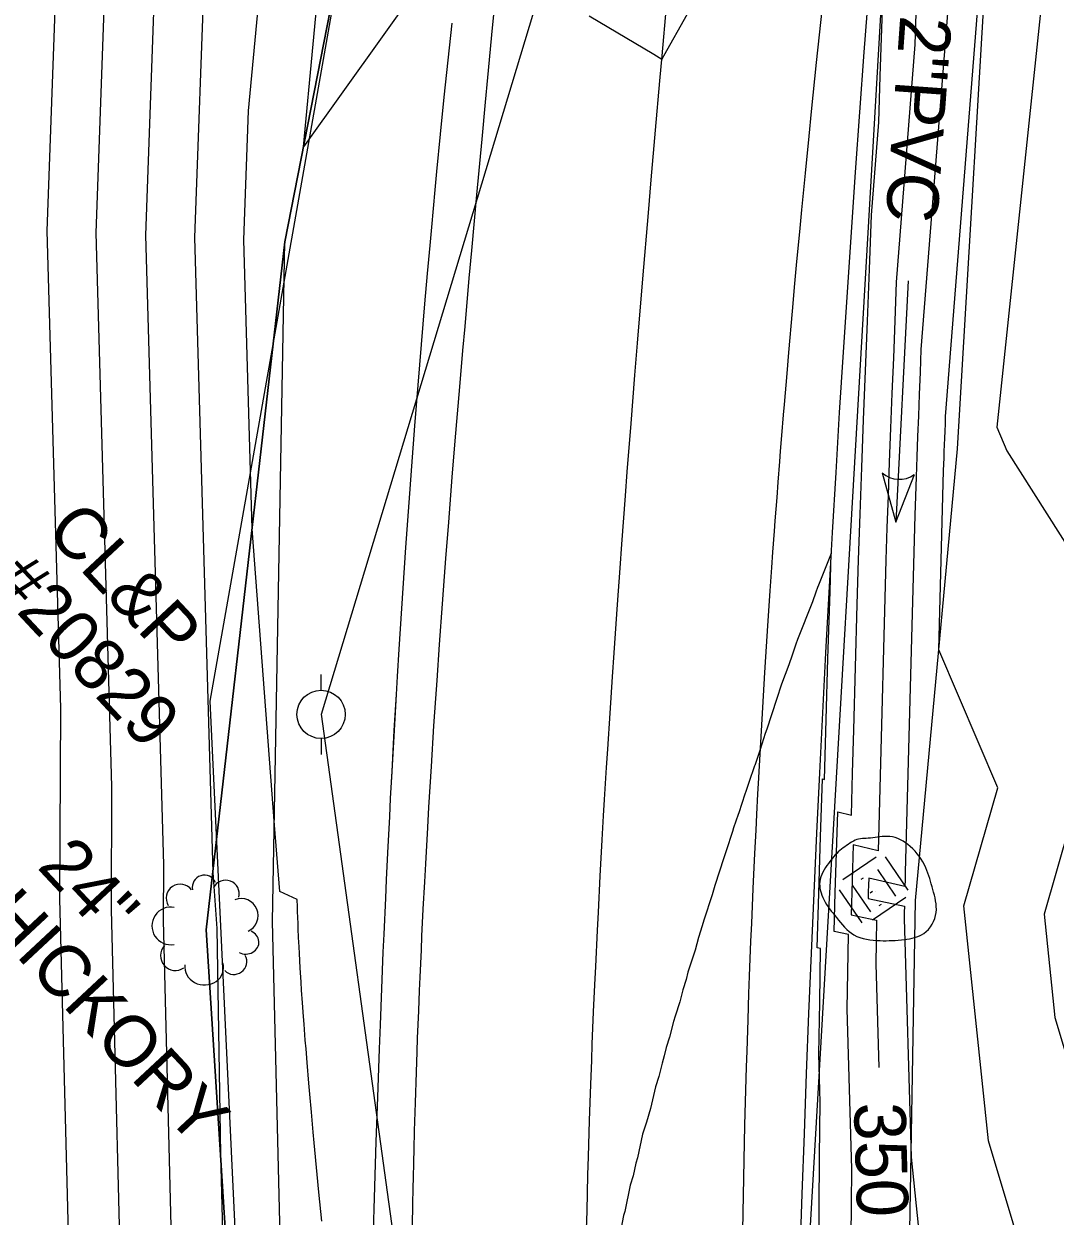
# Model space of a CAD drawing. Extents: x 487096 to 489566, y 221939 to 224454.
# Drawn here: x 488373.2 to 488437.3, y 222981.8 to 223055.9 of the extents above; entities that cross this region are included whole.
import ezdxf

# ---------------------------------------------------------------- set-up
doc = ezdxf.new("R2010")
doc.units = 0
for name, color, linetype in [('SV_BKLN_EARTH_TOP', 7, 'Continuous'), ('SV_FENC_FENCES', 7, 'Continuous'), ('SV_MISC_MISC_TOPO', 7, 'Continuous'), ('SV_PIPE_FLOW', 7, 'Continuous'), ('SV_PIPE_PLAS_12', 7, 'Continuous'), ('SV_PIPE_PLAS_TX', 7, 'Continuous'), ('SV_ROAD_BITRD', 7, 'Continuous'), ('SV_ROCK_MISC_ROCK', 7, 'Continuous'), ('SV_ROWL_HWYLOC', 7, 'Continuous'), ('SV_SURF_INDEX_CONTOUR', 7, 'Continuous'), ('SV_SURF_INTER_CONTOUR', 7, 'Continuous'), ('SV_TRAF_PVMTL', 7, 'Continuous'), ('SV_TREE_TREEVEG', 7, 'Continuous'), ('SV_TREE_TREEVEG_TX', 7, 'Continuous'), ('SV_UTOH_OVERHEAD_LINES', 7, 'Continuous'), ('SV_UTOH_UPO', 7, 'Continuous'), ('SV_UTOH_UTOH_TX', 7, 'Continuous')]:
    doc.layers.add(name, color=color, linetype=linetype)

msp = doc.modelspace()

# ---------------------------------------------------------------- linework, layer by layer
at = {"layer": 'SV_BKLN_EARTH_TOP'}
for points in [[(488425.924, 222945.038), (488428.157, 222977.235), (488428.574, 223001.384), (488431.193, 223029.446), (488433.274, 223064.759), (488435.624, 223093.089), (488438.489, 223133.722), (488441.679, 223167.826), (488447.058, 223190.641), (488452.004, 223226.545)], [(488391.814, 222875.894), (488390.567, 222921.008), (488388.639, 223000.073), (488389.407, 223042.325), (488396.478, 223078.484), (488405.528, 223123.261), (488407.475, 223152.677)]]:
    msp.add_lwpolyline(points, dxfattribs=at)
at = {"layer": 'SV_FENC_FENCES'}
msp.add_lwpolyline([(488400.559, 222861.835), (488391.815, 222875.913), (488387.651, 222918.235), (488386.769, 222964.099), (488384.515, 222999.563), (488389.407, 223042.325), (488396.478, 223078.484), (488402.804, 223123.48), (488407.475, 223152.677), (488415.007, 223209.78), (488415.388, 223241.145)], dxfattribs=at)
at = {"layer": 'SV_MISC_MISC_TOPO'}
msp.add_line((488426.063, 223001.932), (488426.063, 223001.932), dxfattribs=at)
at = {"layer": 'SV_PIPE_FLOW'}
for p, q in [((488428.127, 223039.883), (488427.348, 223024.902)), ((488426.504, 223027.951), (488427.348, 223024.902)), ((488427.348, 223024.902), (488428.505, 223027.848))]:
    msp.add_line(p, q, dxfattribs=at)
msp.add_arc((488427.572, 223029.196), 1.639, 229.42502, 304.62665, dxfattribs=at)
at = {"layer": 'SV_PIPE_PLAS_12'}
msp.add_line((488420.272, 222950.354), (488430.688, 223129.857), dxfattribs=at)
at = {"layer": 'SV_ROAD_BITRD'}
for points in [[(488421.42, 222979.418), (488421.543, 222983.156), (488421.674, 222986.894), (488421.812, 222990.631), (488421.959, 222994.368), (488422.114, 222998.105), (488422.276, 223001.841), (488422.447, 223005.577), (488422.625, 223009.312), (488422.812, 223013.048), (488423.007, 223016.783), (488423.209, 223020.517), (488423.42, 223024.251), (488423.638, 223027.984), (488423.865, 223031.717), (488424.099, 223035.45), (488424.342, 223039.182), (488424.592, 223042.913), (488424.851, 223046.644), (488425.117, 223050.375), (488425.392, 223054.104), (488425.674, 223057.833)], [(488399.764, 223055.907), (488399.444, 223052.836), (488399.287, 223051.301), (488399.056, 223048.997), (488398.831, 223046.693), (488398.72, 223045.54), (488398.504, 223043.235), (488398.398, 223042.083), (488398.242, 223040.353), (488398.075, 223038.461), (488397.967, 223037.2), (488397.756, 223034.677), (488397.653, 223033.415), (488397.453, 223030.891), (488397.26, 223028.366), (488397.136, 223026.682), (488397.055, 223025.56), (488396.897, 223023.314), (488396.81, 223022.051), (488396.643, 223019.524), (488396.483, 223016.997), (488396.379, 223015.312), (488396.312, 223014.188), (488396.182, 223011.941), (488396.042, 223009.412), (488395.952, 223007.725), (488395.894, 223006.601), (488395.781, 223004.352), (488395.7, 223002.665), (488395.647, 223001.54), (488395.546, 222999.291), (488395.497, 222998.166), (488395.402, 222995.916), (488395.313, 222993.665), (488395.256, 222992.165), (488395.148, 222989.163), (488395.055, 222986.385), (488395.012, 222984.995), (488394.95, 222982.911), (488394.894, 222980.827)], [(488399.764, 223055.907), (488399.444, 223052.836), (488399.287, 223051.301), (488399.056, 223048.997), (488398.831, 223046.693), (488398.721, 223045.54), (488398.504, 223043.235), (488398.398, 223042.083), (488398.242, 223040.353), (488398.075, 223038.461), (488397.967, 223037.2), (488397.755, 223034.677), (488397.653, 223033.415), (488397.453, 223030.891), (488397.26, 223028.366), (488397.135, 223026.682), (488397.054, 223025.56), (488396.896, 223023.314), (488396.81, 223022.051), (488396.642, 223019.524), (488396.482, 223016.997), (488396.379, 223015.312), (488396.312, 223014.188), (488396.181, 223011.94), (488396.041, 223009.411), (488395.951, 223007.725), (488395.893, 223006.601), (488395.78, 223004.352), (488395.699, 223002.665), (488395.647, 223001.54), (488395.545, 222999.291), (488395.496, 222998.166), (488395.402, 222995.916), (488395.313, 222993.665), (488395.256, 222992.165), (488395.148, 222989.163), (488395.056, 222986.385), (488395.012, 222984.995), (488394.951, 222982.911), (488394.895, 222980.827)], [(488399.764, 223055.907), (488399.444, 223052.836), (488399.287, 223051.301), (488399.056, 223048.997), (488398.831, 223046.693), (488398.721, 223045.54), (488398.504, 223043.235), (488398.398, 223042.083), (488398.242, 223040.353), (488398.075, 223038.461), (488397.967, 223037.2), (488397.755, 223034.677), (488397.653, 223033.415), (488397.453, 223030.891), (488397.26, 223028.366), (488397.135, 223026.682), (488397.054, 223025.56), (488396.896, 223023.314), (488396.81, 223022.051), (488396.642, 223019.524), (488396.482, 223016.997), (488396.379, 223015.312), (488396.312, 223014.188), (488396.181, 223011.94), (488396.041, 223009.411), (488395.951, 223007.725), (488395.893, 223006.601), (488395.78, 223004.352), (488395.699, 223002.665), (488395.647, 223001.54), (488395.545, 222999.291), (488395.496, 222998.166), (488395.402, 222995.916), (488395.313, 222993.665), (488395.256, 222992.165), (488395.148, 222989.163), (488395.056, 222986.385), (488395.012, 222984.995), (488394.951, 222982.911), (488394.895, 222980.827)]]:
    msp.add_lwpolyline(points, dxfattribs=at)
at = {"layer": 'SV_ROCK_MISC_ROCK'}
for p, q in [((488426.211, 223003.315), (488427.338, 223001.663)), ((488424.648, 223002.338), (488425.779, 223000.688))]:
    msp.add_line(p, q, dxfattribs=at)
for points in [[(488426.128, 223004.078), (488424.063, 223002.666)], [(488426.696, 223004.092), (488428.109, 223002.028)], [(488425.319, 223002.776), (488425.183, 223002.684)], [(488423.831, 223002.057), (488425.242, 222999.995)], [(488425.896, 223001.935), (488425.76, 223001.843)], [(488427.975, 223001.579), (488425.914, 223000.168)], [(488426.438, 223001.141), (488426.307, 223001.049)]]:
    msp.add_lwpolyline(points, dxfattribs=at)
msp.add_spline([(488424.715, 223005.074), (488423.879, 223004.493), (488423.164, 223003.694), (488422.629, 223002.566), (488422.874, 223001.445), (488423.673, 223000.321), (488424.75, 222999.249), (488426.377, 222998.891), (488427.886, 222998.964), (488429.09, 222999.333), (488429.856, 223000.646), (488429.654, 223002.071), (488429.213, 223003.421), (488428.25, 223004.746), (488426.972, 223005.363), (488426.787, 223005.369), (488425.641, 223005.251), (488424.718, 223005.076), (488424.705, 223005.067)], degree=3, dxfattribs=at)
at = {"layer": 'SV_ROWL_HWYLOC'}
msp.add_lwpolyline([(488415.388, 223241.145), (488415.007, 223209.78), (488407.475, 223152.677), (488402.804, 223123.48), (488396.478, 223078.484), (488389.407, 223042.325), (488386.961, 223020.944), (488384.515, 222999.563), (488386.769, 222964.099), (488387.651, 222918.235), (488391.815, 222875.913), (488394, 222859.238), (488415.207, 222774.386)], dxfattribs=at)
at = {"layer": 'SV_SURF_INDEX_CONTOUR'}
for points in [[(488379.351, 222972.188), (488378.624, 223000.814), (488378.664, 223008.462), (488377.682, 223042.865), (488378.243, 223058.541)], [(488428.598, 223056.513), (488428.537, 223054.572), (488427.374, 223039.801), (488427.286, 223037.416), (488427.206, 223035.111), (488427.112, 223032.9), (488427.025, 223030.738), (488426.945, 223028.624), (488426.87, 223026.557), (488426.802, 223024.535), (488426.739, 223022.557), (488426.339, 223007.564), (488426.294, 223006), (488426.253, 223004.478), (488424.711, 223004.835), (488424.66, 223003.346), (488424.613, 223001.897), (488424.571, 223000.486), (488426.153, 223000.155), (488426.128, 222998.79), (488426.106, 222997.459), (488426.291, 222991)]]:
    msp.add_lwpolyline(points, dxfattribs=at)
at = {"layer": 'SV_SURF_INTER_CONTOUR'}
for points in [[(488393.727, 223230.342), (488395.957, 223208.567), (488396.766, 223191.599), (488396.761, 223190.004), (488396.754, 223188.935), (488396.731, 223186.785), (488396.715, 223185.704), (488396.675, 223183.531), (488399.104, 223174.552), (488399.019, 223172.338), (488398.956, 223170.854), (488398.077, 223154.84), (488399.462, 223145.879), (488397.97, 223122.923), (488395.516, 223114.366), (488386.678, 223084.046), (488384.425, 223060.17), (488383.795, 223042.583), (488384.921, 223003.118), (488385.182, 222999.645), (488385.401, 222985.627), (488385.932, 222964.714)], [(488388.002, 223227.487), (488389.978, 223208.186), (488390.695, 223193.147), (488390.691, 223191.733), (488390.684, 223190.786), (488390.664, 223188.88), (488390.65, 223187.922), (488390.615, 223185.996), (488393.85, 223174.037), (488393.772, 223172.014), (488393.714, 223170.658), (488392.911, 223156.028), (488395.058, 223142.143), (488393.778, 223122.441), (488389.196, 223106.462), (488383.231, 223086.001), (488381.711, 223069.889), (488380.739, 223042.724), (488381.855, 223003.609), (488381.837, 223000.132), (488382.676, 222967.106)], [(488376.551, 223221.776), (488378.02, 223207.425), (488378.553, 223196.243), (488378.55, 223195.191), (488378.545, 223194.487), (488378.53, 223193.07), (488378.52, 223192.358), (488378.493, 223190.925), (488383.341, 223173.007), (488383.277, 223171.367), (488383.231, 223170.267), (488382.579, 223158.405), (488386.25, 223134.67), (488385.392, 223121.475), (488376.555, 223090.655), (488376.339, 223089.913), (488376.284, 223089.329), (488374.625, 223043.005), (488375.473, 223013.316), (488375.412, 223001.496), (488376.164, 222971.889)], [(488444.738, 223139.906), (488443.486, 223134.795), (488442.207, 223128.85), (488437.705, 223095.548), (488437.641, 223093.606), (488437.615, 223090.913), (488437.236, 223067.257), (488438.303, 223064.405), (488437.196, 223062.974), (488436.493, 223057.978), (488433.618, 223030.808), (488434.258, 223029.334), (488441.028, 223018.654), (488441.049, 223018.096), (488440.962, 223017.32), (488440.482, 223014.189), (488436.564, 223000.533), (488437.239, 222994.108), (488442.853, 222975.364)], [(488391.692, 222981.463), (488391.519, 222983.268), (488391.415, 222984.36), (488391.232, 222986.321), (488391.17, 222986.988), (488391.058, 222988.227), (488390.957, 222989.351), (488390.897, 222990.044), (488390.787, 222991.314), (488390.716, 222992.176), (488390.672, 222992.713), (488390.593, 222993.708), (488390.557, 222994.169), (488390.494, 222995.028), (488390.439, 222995.814), (488390.406, 222996.302), (488390.35, 222997.204), (488390.301, 222998.086), (488390.281, 222998.496), (488390.254, 222999.08), (488390.231, 222999.63), (488390.221, 222999.893), (488390.204, 223000.4), (488390.196, 223000.644), (488390.186, 223001), (488390.175, 223001.455), (488389.082, 223001.948), (488388.748, 223006.075), (488387.365, 223024.474), (488386.852, 223042.443), (488387.138, 223050.45), (488390.124, 223082.09)], [(488400.328, 223061.911), (488390.558, 223048.214), (488393.57, 223080.134)], [(488436.184, 222976.213), (488433.118, 222986.451), (488431.583, 223001.063), (488433.686, 223008.391), (488430.028, 223016.964), (488430.325, 223028.103), (488430.337, 223028.489), (488430.351, 223028.883), (488430.365, 223029.286), (488430.381, 223029.697), (488430.398, 223030.119), (488430.416, 223030.55), (488430.432, 223030.999), (488430.449, 223031.463), (488433.028, 223064.23)], [(488430.783, 223059.401), (488428.912, 223035.632), (488428.859, 223034.208), (488428.811, 223032.831), (488428.755, 223031.509), (488428.703, 223030.218), (488428.655, 223028.955), (488428.61, 223027.72), (488428.57, 223026.512), (488428.532, 223025.33), (488427.94, 223003.137), (488427.927, 223002.693), (488427.916, 223002.261), (488425.667, 223002.783), (488425.652, 223002.346), (488425.638, 223001.922), (488425.626, 223001.509), (488427.887, 223001.035), (488427.88, 223000.648), (488427.874, 223000.271), (488428.299, 222985.434), (488428.996, 222978.793)], [(488424.583, 222980.435), (488424.601, 222982.533), (488424.623, 222984.696), (488424.338, 222994.648), (488424.376, 222996.931), (488424.419, 222999.275), (488423.516, 222999.464), (488423.588, 223001.873), (488423.668, 223004.346), (488423.755, 223006.888), (488424.59, 223006.695), (488424.66, 223009.306), (488424.739, 223011.992), (488424.946, 223019.783), (488425.034, 223022.558), (488425.13, 223025.394), (488425.234, 223028.293), (488425.347, 223031.258), (488425.47, 223034.29), (488425.601, 223037.392), (488425.714, 223040.625), (488425.837, 223043.969), (488426.292, 223049.743), (488426.381, 223052.603), (488426.481, 223055.577), (488426.592, 223058.67)], [(488414.394, 223056.462), (488412.931, 223053.861), (488412.817, 223053.655), (488412.325, 223053.949), (488408.3, 223056.348)], [(488422.574, 222979.044), (488422.594, 222982.216), (488422.621, 222985.483), (488422.656, 222988.85), (488422.57, 222991.837), (488422.624, 222995.073), (488422.685, 222998.395), (488422.461, 222998.442), (488422.563, 223001.848), (488422.676, 223005.346), (488422.798, 223008.941), (488422.926, 223008.911), (488423.027, 223012.613), (488423.138, 223016.42), (488423.153, 223017.01), (488423.266, 223020.581), (488423.347, 223022.954), (488422.556, 223020.99), (488422.495, 223020.83), (488422.387, 223020.541), (488422.171, 223019.953), (488421.252, 223017.596), (488421.15, 223017.305), (488420.916, 223016.635), (488420.71, 223016.037), (488420.254, 223014.832), (488419.938, 223013.871), (488419.34, 223012.027), (488419.241, 223011.755), (488418.936, 223010.761), (488418.596, 223009.782), (488418.584, 223009.748), (488418.232, 223008.725), (488418.035, 223008.149), (488417.983, 223007.988), (488417.593, 223006.839), (488417.555, 223006.72), (488417.277, 223005.893), (488417.207, 223005.668), (488416.807, 223004.47), (488416.675, 223004.028), (488416.113, 223002.326), (488415.944, 223001.74), (488415.433, 223000.173), (488415.334, 222999.818), (488415.099, 222999.092), (488414.882, 222998.293), (488414.442, 222996.924), (488414.322, 222996.467), (488414.12, 222995.836), (488413.93, 222995.092), (488413.646, 222994.2), (488413.541, 222993.87), (488413.298, 222992.888), (488413.098, 222992.254), (488412.971, 222991.726), (488412.83, 222991.279), (488412.632, 222990.441), (488412.435, 222989.813), (488412.123, 222988.451), (488411.861, 222987.606), (488411.627, 222986.864), (488411.309, 222985.392), (488411.205, 222985.062), (488411.041, 222984.283), (488410.856, 222983.691), (488410.524, 222982.058), (488410.444, 222981.802), (488410.274, 222980.943)]]:
    msp.add_lwpolyline(points, dxfattribs=at)
at = {"layer": 'SV_TRAF_PVMTL'}
for points in [[(488402.628, 223059.065), (488402.289, 223055.609), (488401.993, 223052.537), (488401.846, 223051.001), (488401.629, 223048.696), (488401.308, 223045.239), (488400.993, 223041.781), (488400.837, 223040.051), (488400.572, 223037.057), (488400.442, 223035.56), (488400.249, 223033.314), (488399.966, 223029.944), (488399.782, 223027.697), (488399.691, 223026.574), (488399.558, 223024.888), (488399.383, 223022.641), (488399.298, 223021.517), (488399.172, 223019.83), (488398.989, 223017.301), (488398.832, 223015.052), (488398.755, 223013.928), (488398.643, 223012.241), (488398.482, 223009.71), (488398.328, 223007.18), (488398.254, 223005.914), (488398.129, 223003.664), (488398.068, 223002.539), (488397.981, 223000.851), (488397.899, 222999.162), (488397.859, 222998.318), (488397.782, 222996.63), (488397.746, 222995.786), (488397.693, 222994.519), (488397.627, 222992.831), (488397.596, 222991.986), (488397.551, 222990.72), (488397.489, 222988.819), (488397.438, 222987.075), (488397.406, 222985.912), (488397.387, 222985.136), (488397.362, 222984.102), (488397.351, 222983.585), (488397.326, 222982.422), (488397.284, 222980.095)], [(488408.145, 222980.959), (488408.171, 222982.084), (488408.227, 222984.334), (488408.259, 222985.46), (488408.329, 222987.71), (488408.406, 222989.961), (488408.462, 222991.462), (488408.501, 222992.462), (488408.584, 222994.463), (488408.659, 222996.151), (488408.71, 222997.276), (488408.819, 222999.527), (488408.876, 223000.653), (488408.994, 223002.904), (488409.119, 223005.154), (488409.205, 223006.655), (488409.264, 223007.655), (488409.385, 223009.656), (488409.455, 223010.781), (488409.6, 223013.031), (488409.749, 223015.281), (488409.851, 223016.781), (488410.061, 223019.781), (488410.223, 223022.03), (488410.334, 223023.53), (488410.56, 223026.529), (488410.675, 223028.028), (488410.91, 223031.025), (488411.149, 223034.022), (488411.312, 223036.02), (488411.641, 223040.014), (488411.986, 223044.119), (488412.161, 223046.172), (488412.427, 223049.249), (488412.698, 223052.326), (488412.835, 223053.865), (488413.114, 223056.94)], [(488417.848, 222980.886), (488417.866, 222981.976), (488417.907, 222984.157), (488417.93, 222985.247), (488417.981, 222987.427), (488418.038, 222989.606), (488418.08, 222991.059), (488418.11, 222992.028), (488418.152, 222993.319), (488418.173, 222993.965), (488418.231, 222995.599), (488418.271, 222996.688), (488418.357, 222998.866), (488418.402, 222999.955), (488418.497, 223002.133), (488418.598, 223004.31), (488418.669, 223005.761), (488418.718, 223006.729), (488418.785, 223008.019), (488418.82, 223008.663), (488418.879, 223009.751), (488419.002, 223011.927), (488419.131, 223014.103), (488419.221, 223015.553), (488419.282, 223016.519), (488419.365, 223017.808), (488419.407, 223018.452), (488419.554, 223020.626), (488419.655, 223022.075), (488419.724, 223023.041), (488419.818, 223024.329), (488419.865, 223024.973), (488419.974, 223026.421), (488420.048, 223027.386), (488420.148, 223028.674), (488420.199, 223029.317), (488420.277, 223030.282), (488420.381, 223031.569), (488420.434, 223032.212), (488420.596, 223034.142), (488420.707, 223035.428), (488420.933, 223038), (488421.089, 223039.719), (488421.194, 223040.864), (488421.409, 223043.155), (488421.519, 223044.301), (488421.741, 223046.591), (488421.969, 223048.881), (488422.122, 223050.407), (488422.434, 223053.46), (488422.793, 223056.893)]]:
    msp.add_lwpolyline(points, dxfattribs=at)
at = {"layer": 'SV_TREE_TREEVEG'}
msp.add_line((488384.515, 222999.563), (488384.515, 222999.563), dxfattribs=at)
msp.add_lwpolyline([(488469.572, 222626.729), (488414.357, 222775.799), (488391.306, 222875.646), (488384.757, 223013.776), (488396.275, 223079.007), (488413.65, 223210.141), (488414.482, 223247.549), (488427.956, 223341.619), (488424.883, 223443.612), (488411.442, 223499.763), (488395.395, 223528.757), (488373.339, 223524.504)], dxfattribs=at)
for centre, radius, start, end in [((488384.404, 223002.214), 0.75, 23.2911, 192.35792), ((488385.719, 223001.8), 0.85, 345.53076, 152.70931), ((488382.904, 223001.527), 0.874, 35.99331, 211.459), ((488386.68, 223000.444), 1.059, 294.18586, 111.10825), ((488382.315, 222999.809), 1.171, 79.3292, 279.98885), ((488382.598, 222997.959), 0.922, 137.01566, 304.55007)]:
    msp.add_arc(centre, radius, start, end, dxfattribs=at)
for centre, major_axis, ratio, start_param, end_param in [((488386.97, 222998.796), (0.822, -0.013), 0.901056, 4.216583, 7.444153), ((488384.386, 222997.227), (-1.196, 0.159), 0.902156, 0, 3.5401), ((488386.234, 222997.594), (0.08, -0.798), 0.999752, 5.391582, 8.241319)]:
    msp.add_ellipse(centre, major_axis=major_axis, ratio=ratio, start_param=start_param, end_param=end_param, dxfattribs=at)
at = {"layer": 'SV_UTOH_OVERHEAD_LINES'}
msp.add_lwpolyline([(488477.012, 222631.438), (488424.125, 222778.25), (488391.68, 223012.955), (488449.873, 223205.72), (488469.995, 223438.334), (488349.561, 223622.886), (488159.178, 223693.118), (487993.175, 223755.783), (487804.196, 223830.216), (487742.262, 223860.212)], dxfattribs=at)
at = {"layer": 'SV_UTOH_UPO'}
for p, q in [((488391.658, 223014.429), (488391.658, 223015.431)), ((488391.671, 223010.457), (488391.671, 223011.456))]:
    msp.add_line(p, q, dxfattribs=at)
msp.add_circle((488391.651, 223012.95), 1.5, dxfattribs=at)

# ---------------------------------------------------------------- texts
at = {"layer": 'SV_PIPE_PLAS_TX'}
msp.add_text("12''PVC", height=3.2, rotation=265.91172, dxfattribs=at).set_placement((488427.804, 223058.799))
at = {"layer": 'SV_SURF_INDEX_CONTOUR'}
msp.add_text('350', height=3.2, rotation=271.64009, dxfattribs=at).set_placement((488424.753, 222988.807))
at = {"layer": 'SV_TREE_TREEVEG_TX'}
for s, p in [('24"', (488373.952, 223003.444)), ('HICKORY', (488370.516, 223000.236))]:
    msp.add_text(s, height=3.2, rotation=313.03859, dxfattribs=at).set_placement(p)
at = {"layer": 'SV_UTOH_UTOH_TX'}
for s, p in [('CL&P', (488374.476, 223024.274)), ('#20829', (488371.041, 223021.066))]:
    msp.add_text(s, height=3.2, rotation=313.03859, dxfattribs=at).set_placement(p)

doc.saveas('drawing.dxf')
